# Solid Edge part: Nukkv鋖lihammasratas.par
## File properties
Author: Türk
Template: Iso Part.par
Last saved by: Türk
Revision: 10
Application: Solid Edge
Accuracy: 0,990
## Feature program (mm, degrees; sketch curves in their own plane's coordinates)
pattern "PatternOccurrence_3"  XOffset = 45 deg
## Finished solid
Body 1: solid body, 82 faces, 234 edges, 148 vertices.
  Faces by surface: plane 47, cylinder 23, torus 12
  Edges by curve: line 140, circle 70, intersection 24
Bounding box of the edges (mm; curved faces can reach further): 85.000 x 24.000 x 85.000, from (-42.5, 0, -42.5) to (42.5, 24, 42.5).
Cylindrical faces by radius (mm): R9 x8, R11 x6, R35 x6, R40 x1, R42.5 x2
Toroidal faces (ring radius, tube radius in mm): R16 r5 x6, R22.7849 r5 x6
Planar faces by outward normal: +y 2, +z 2, -y 9, -z 2, oblique 32
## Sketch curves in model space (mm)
line (-3.0218, 0, 10.6034) -> (-3.0165, 0, 10.5783)
line (-1.5493, 0, 10.8904) -> (-1.5546, 0, 10.9154)
line (1, 24, 35.0858) -> (1, 24, 35.1)
line (-1, 24, 35.0858) -> (-1, 24, 35.1)
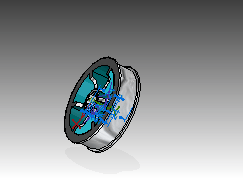
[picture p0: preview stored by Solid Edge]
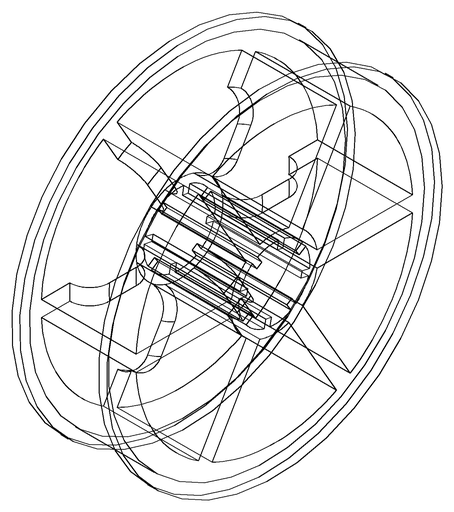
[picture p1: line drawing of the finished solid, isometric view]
